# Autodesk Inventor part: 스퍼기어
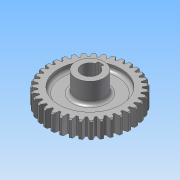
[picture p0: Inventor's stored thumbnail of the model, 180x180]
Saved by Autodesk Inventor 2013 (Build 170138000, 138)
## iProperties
Created: 2013-08
Part Number: 스퍼기어
Material: 강
Document SubType Name: Modeling
Designer: 한국산업디자인학원
Categories: <?xml version="1.0" encoding="UTF-16"?> <MemberInstance><Categories><FamilyTemplate><FamilyTemplateParameter ValueType="xs:double" Id="1" ObjectReferenceKey="da
Density: 1 g/cm^3
CustomPartVersion: 1
Author: 한국산업디자인학원
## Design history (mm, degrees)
sketch "Sketch1"
  geometry: C1 r 37 at (0, 0)
  constraints: 1 centre point
  dimensions: "d0" = 74 diameter of C1 (= da_da)
extrude "Extrusion1" new body sketch "Sketch1" distance "d1" = 15 (= da_b); taper "d2" = 0 deg
chamfer "모따기1" distance "d49" = 1; stored, may be unused: second distance "d50" = 2, angle "d51" = 45 deg
workplane "Work Plane2"
feature "피치 지름" dims "d4" = 10, "d5" = 0
workplane "Work Plane8"
workplane "Work Plane9"
feature "스퍼 기어" dims "da_b" = 15, "da_d" = 70, "da_aw" = 70, "da_da" = 74, "da_df" = 65, "da_dw" = 70, angle "da_beta" = 0 deg, "da_lefttooth" = 0, "da_righttooth" = 0
node "작업 평면11"
sketch "스케치3"
  geometry: C1 r 12.5 at (0, 0); 1 further point
  constraints: 1 centre point, 1 coincident
  dimensions: "d53" = 25 diameter of C1
extrude "돌출2" join sketch "스케치3" distance "d56" = 31; taper "d57" = 0 deg
sketch "스케치4"
  geometry: L1 (-2.5, 7.071)-(-2.5, 9.8); L2 (-2.5, 9.8)-(2.5, 9.8); L3 (2.5, 9.8)-(2.5, 7.071); C1 r 12.5 at (0, 0) reference; A1 r 7.5 centre (0, 0) between (-2.5, 7.071) and (2.5, 7.071)
  constraints: 6 end point, 2 parallel, 2 point on circle, 1 centre point, 1 coincident, 1 perpendicular, 1 vertical
  dimensions: "d58" = 15 diameter of A1; "d60" = 5 distance of L1.end L2.end; "d61" = 17.3 dimension on A1 L2
extrude "돌출3" cut sketch "스케치4" stored distance "d62" = 31; taper "d63" = 0 deg
sketch "스케치5"
  geometry: L1 (-2.5, 7.071)-(-2.5, 9.8) reference; L2 (-2.5, 9.8)-(2.5, 9.8) reference; L3 (2.5, 9.8)-(2.5, 7.071) reference; C1 r 12.5 at (0, 0) reference; C2 r 12.5 at (0, 0) reference; C3 r 27.5 at (0, 0); A1 r 7.5 centre (0, 0) between (-2.5, 7.071) and (2.5, 7.071) reference
  constraints: 1 centre point, 1 coincident
  dimensions: "d64" = 55 diameter of C3
extrude "돌출4" cut sketch "스케치5" distance "d66" = 5; taper "d67" = 0 deg
node "작업 평면12"
fillet "모깎기1" dims "d69" = 3
body "Solid1"
mirror "대칭1"
sketch "Sketch2"
  geometry: C1 r 37 at (0, 0) reference; C2 r 35 at (0, 0)
  constraints: 1 centre point, 1 coincident
  dimensions: "d3" = 70 diameter of C2 (= da_dw)
body "Srf1"
node "투영된 루프1"
other parameters: "d17" = 0, "d34" = 0.8976 (computed from da_z), "d39" = 0, "d41" = 0, "d47" = 0, "d48" = 0, "d52" = 3, "d68" = -7.5
